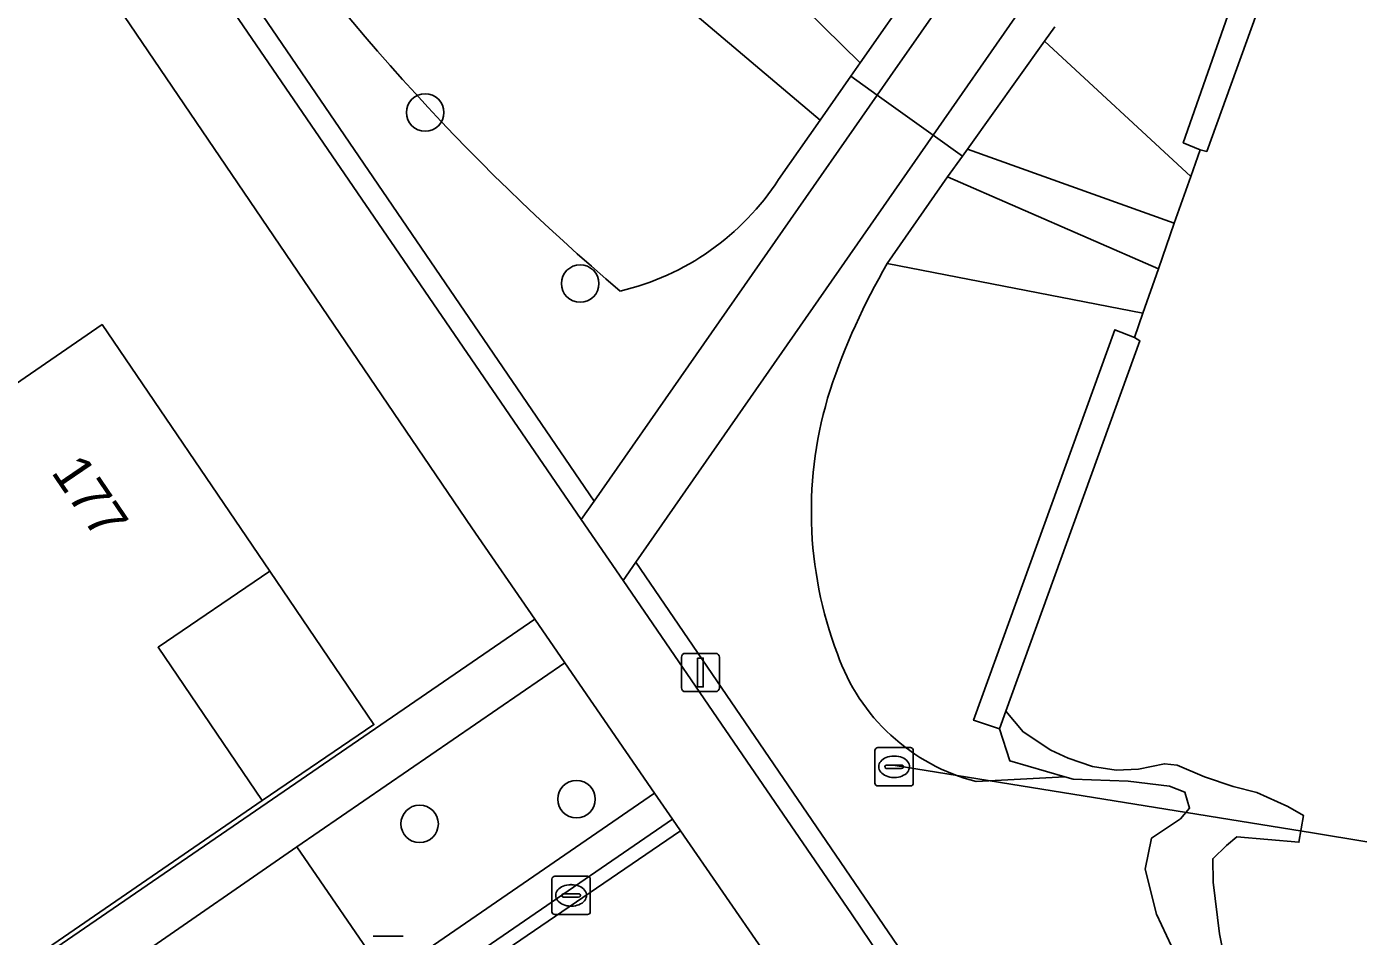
# Model space of a CAD drawing. Extents: x 155275 to 156265, y 382654 to 383635.
# Drawn here: x 155762.83 to 155797.88, y 383396.14 to 383419.88 of the extents above; entities that cross this region are included whole.
import ezdxf

# ---------------------------------------------------------------- set-up
doc = ezdxf.new("R2010")
doc.units = 0
for name, color, linetype in [('IMGEO_Boom', 7, 'Continuous'), ('IMGEO_Duiker', 7, 'Continuous'), ('IMGEO_Erf', 7, 'Continuous'), ('IMGEO_Groenvoorziening', 7, 'Continuous'), ('IMGEO_Haag', 7, 'Continuous'), ('IMGEO_Kademuur', 7, 'Continuous'), ('IMGEO_Kolk', 7, 'Continuous'), ('IMGEO_Lichtmast', 7, 'Continuous'), ('IMGEO_Meer_plas_ven_vijver', 7, 'Continuous'), ('IMGEO_Oever', 7, 'Continuous'), ('IMGEO_Pand', 7, 'Continuous'), ('IMGEO_Pand_nummerreeks', 7, 'Continuous'), ('IMGEO_Pand_overbouw', 7, 'Continuous'), ('IMGEO_Parkeervlak_open', 7, 'Continuous'), ('IMGEO_Rijbaan_lokaal_gesloten', 7, 'Continuous'), ('IMGEO_Rijbaan_lokaal_open', 7, 'Continuous'), ('IMGEO_Rioolput', 7, 'Continuous'), ('IMGEO_Voetpad_halfverhard', 7, 'Continuous'), ('IMGEO_Voetpad_open', 7, 'Continuous'), ('IMGEO_Waterloop', 7, 'Continuous')]:
    doc.layers.add(name, color=color, linetype=linetype)

msp = doc.modelspace()

# ---------------------------------------------------------------- linework, layer by layer
at = {"layer": 'IMGEO_Boom'}
for centre in [(155773.231, 383417.64), (155777.279, 383413.176), (155777.183, 383399.719), (155773.086, 383399.074)]:
    msp.add_circle(centre, 0.489, dxfattribs=at)
at = {"layer": 'IMGEO_Duiker'}
for points in [[(155787.259, 383416.5), (155786.497, 383417.047), (155785.035, 383418.096), (155784.346, 383418.59)], [(155797.819, 383398.608), (155796.402, 383398.837), (155785.502, 383400.6)]]:
    msp.add_lwpolyline(points, dxfattribs=at)
at = {"layer": 'IMGEO_Erf'}
for points in [[(155734.512, 383465.559), (155725.215, 383479.049), (155698.054, 383460.537), (155694.998, 383458.429), (155719.873, 383421.949), (155720.07, 383422.058), (155723.062, 383417.667), (155735.929, 383398.789), (155735.874, 383398.763), (155746.045, 383383.83), (155750.929, 383387.164), (155776.093, 383404.417), (155774.449, 383406.803)], [(155755.264, 383402.793), (155753.973, 383404.673), (155764.793, 383412.107), (155769.172, 383405.667), (155766.255, 383403.684), (155768.977, 383399.681), (155761.042, 383394.237), (155758.839, 383397.452), (155755.091, 383394.96), (155751.995, 383399.56), (155751.574, 383399.282), (155751.13, 383399.955)]]:
    msp.add_lwpolyline(points, close=True, dxfattribs=at)
at = {"layer": 'IMGEO_Groenvoorziening'}
for points in [[(155720.532, 383490.035), (155723.759, 383485.312), (155724.227, 383485.725), (155777.645, 383407.499), (155785.035, 383418.096), (155785.37, 383418.576), (155786.992, 383420.901), (155789.946, 383428.782), (155786.989, 383433.092)], [(155792.313, 383430.497), (155782.858, 383445.59), (155782.062, 383443.394), (155782.026, 383443.296), (155791.926, 383428.938), (155788.632, 383420.112), (155786.497, 383417.047), (155778.735, 383405.903), (155812.556, 383356.375)], [(155789.67, 383419.875), (155789.407, 383419.506), (155793.222, 383415.974), (155793.465, 383416.67), (155793.028, 383416.849), (155795.838, 383424.87), (155801.017, 383438.651), (155801.583, 383440.095), (155802.044, 383439.848)], [(155786.452, 383421.955), (155786.323, 383421.662), (155786.199, 383421.367), (155786.078, 383421.07), (155784.59, 383418.94), (155784.346, 383418.59), (155783.545, 383417.443), (155782.462, 383415.892)], [(155785.297, 383413.698), (155786.874, 383415.961), (155787.259, 383416.5), (155787.391, 383416.684), (155789.407, 383419.506), (155789.67, 383419.875)], [(155789.937, 383400.304), (155788.501, 383400.718), (155788.229, 383401.557), (155787.554, 383401.779), (155791.239, 383411.971), (155791.75, 383411.768), (155791.972, 383412.404), (155785.297, 383413.698)], [(155789.937, 383400.304), (155787.621, 383400.178)], [(155787.621, 383400.178), (155789.937, 383400.304)], [(155793.24, 383394.77), (155792.326, 383396.718), (155792.029, 383397.89), (155792.2, 383398.702), (155792.957, 383399.208), (155793.191, 383399.488), (155793.07, 383399.904), (155792.665, 383400.062), (155791.585, 383400.188), (155790.156, 383400.241), (155789.937, 383400.304)]]:
    msp.add_lwpolyline(points, dxfattribs=at)
for points in [[(155724.227, 383485.725), (155723.759, 383485.312), (155746.216, 383452.521), (155760.092, 383432.137), (155777.308, 383407.016), (155777.645, 383407.499)], [(155778.735, 383405.903), (155778.4, 383405.423), (155781.629, 383400.711), (155784.362, 383396.723), (155785.107, 383395.628), (155804.649, 383366.907), (155818.089, 383347.327), (155825.267, 383336.869), (155825.684, 383337.436), (155820.541, 383344.855), (155818.47, 383347.843), (155812.556, 383356.375)], [(155776.879, 383403.277), (155769.879, 383398.475), (155772.222, 383395.062), (155779.221, 383399.877)]]:
    msp.add_lwpolyline(points, close=True, dxfattribs=at)
for centre, radius, start, end in [((155816.344, 383457.794), 58.77, 214.23276, 229.68994), ((155776.754, 383419.603), 6.808, 283.3333, 326.9735), ((155800.504, 383404.845), 17.596, 149.7948, 161.6157), ((155800.504, 383404.845), 17.596, 149.7948, 161.6157), ((155793.797, 383407.226), 10.481, 162.404, 200.7737), ((155793.797, 383407.226), 10.481, 162.404, 200.7737), ((155788.917, 383405.224), 5.21, 199.2229, 255.6018), ((155788.917, 383405.224), 5.21, 199.2229, 255.6018)]:
    msp.add_arc(centre, radius, start, end, dxfattribs=at)
at = {"layer": 'IMGEO_Haag'}
for points in [[(155724.227, 383485.725), (155723.759, 383485.312), (155746.216, 383452.521), (155760.092, 383432.137), (155777.308, 383407.016), (155777.645, 383407.499)], [(155778.735, 383405.903), (155778.4, 383405.423), (155781.629, 383400.711), (155784.362, 383396.723), (155785.107, 383395.628), (155804.649, 383366.907), (155818.089, 383347.327), (155825.267, 383336.869), (155825.684, 383337.436), (155820.541, 383344.855), (155818.47, 383347.843), (155812.556, 383356.375)]]:
    msp.add_lwpolyline(points, close=True, dxfattribs=at)
at = {"layer": 'IMGEO_Kademuur'}
for points in [[(155800.706, 383436.152), (155801.722, 383438.959), (155802.044, 383439.848), (155801.583, 383440.095), (155801.017, 383438.651), (155795.838, 383424.87), (155793.028, 383416.849), (155793.465, 383416.67), (155793.639, 383416.625)], [(155788.229, 383401.557), (155788.397, 383402.02), (155791.895, 383411.685), (155791.75, 383411.768), (155791.239, 383411.971), (155787.554, 383401.779)]]:
    msp.add_lwpolyline(points, close=True, dxfattribs=at)
at = {"layer": 'IMGEO_Kolk'}
for p, q in [((155776.617, 383397.708), (155777.469, 383397.708)), ((155776.542, 383396.782), (155776.542, 383397.634)), ((155777.03, 383397.488), (155777.055, 383397.488)), ((155777.543, 383397.634), (155777.543, 383396.782)), ((155776.801, 383397.202), (155776.801, 383397.214)), ((155777.239, 383397.165), (155776.841, 383397.165)), ((155776.844, 383397.251), (155777.242, 383397.251)), ((155777.285, 383397.214), (155777.285, 383397.202)), ((155777.469, 383396.708), (155776.617, 383396.708)), ((155777.053, 383396.928), (155777.028, 383396.928))]:
    msp.add_line(p, q, dxfattribs=at)
for points in [[(155776.617, 383397.708), (155777.469, 383397.708)], [(155776.542, 383396.782), (155776.542, 383397.634)], [(155777.543, 383397.634), (155777.543, 383396.782)], [(155777.469, 383396.708), (155776.617, 383396.708)]]:
    msp.add_lwpolyline(points, dxfattribs=at)
for centre, radius, start, end in [((155776.619, 383397.632), 0.0765, 91.552, 178.448), ((155776.619, 383397.632), 0.0765, 91.552, 178.448), ((155777.467, 383397.632), 0.0765, 1.552, 88.448), ((155777.467, 383397.632), 0.0765, 1.552, 88.448), ((155776.841, 383397.211), 0.0403, 85.8775, 175.7526), ((155776.838, 383397.201), 0.0366, 178.938, 274.7102), ((155777.242, 383397.208), 0.043, 264.8664, 352.4533), ((155777.246, 383397.213), 0.0386, 1.7309, 96.639), ((155776.619, 383396.784), 0.0765, 181.552, 268.448), ((155776.619, 383396.784), 0.0765, 181.552, 268.448), ((155777.467, 383396.784), 0.0765, 271.552, 358.448), ((155777.467, 383396.784), 0.0765, 271.552, 358.448)]:
    msp.add_arc(centre, radius, start, end, dxfattribs=at)
for centre, major_axis, ratio, start_param, end_param in [((155777.029, 383397.208), (-0.387, 0.002), 0.722429, 4.712389, 7.853982), ((155777.054, 383397.208), (-0.39, 0.002), 0.717154, 1.570796, 4.712389)]:
    msp.add_ellipse(centre, major_axis=major_axis, ratio=ratio, start_param=start_param, end_param=end_param, dxfattribs=at)
at = {"layer": 'IMGEO_Lichtmast'}
for p, q in [((155779.924, 383402.625), (155779.924, 383403.425)), ((155779.924, 383403.425), (155779.924, 383402.625)), ((155780.024, 383403.525), (155780.814, 383403.525)), ((155780.814, 383403.525), (155780.024, 383403.525)), ((155780.914, 383403.425), (155780.914, 383402.625)), ((155780.914, 383402.625), (155780.914, 383403.425)), ((155780.814, 383402.525), (155780.024, 383402.525)), ((155780.024, 383402.525), (155780.814, 383402.525)), ((155771.869, 383396.145), (155772.659, 383396.145)), ((155772.659, 383396.145), (155771.869, 383396.145))]:
    msp.add_line(p, q, dxfattribs=at)
msp.add_lwpolyline([(155780.344, 383403.4), (155780.494, 383403.4), (155780.494, 383402.65), (155780.344, 383402.65), (155780.344, 383403.4)], dxfattribs=at)
for centre, start, end in [((155780.024, 383403.425), 90, 180), ((155780.024, 383403.425), 90, 180), ((155780.814, 383403.425), 0, 90), ((155780.814, 383403.425), 360, 90), ((155780.024, 383402.625), 180, 270), ((155780.024, 383402.625), 180, 270), ((155780.814, 383402.625), 270, 0), ((155780.814, 383402.625), 270, 0)]:
    msp.add_arc(centre, 0.1, start, end, dxfattribs=at)
at = {"layer": 'IMGEO_Meer_plas_ven_vijver'}
msp.add_lwpolyline([(155800.706, 383436.152), (155793.639, 383416.625), (155793.465, 383416.67), (155793.222, 383415.974), (155792.794, 383414.752), (155792.377, 383413.56), (155791.972, 383412.404), (155791.75, 383411.768), (155791.895, 383411.685), (155788.397, 383402.02), (155788.847, 383401.476), (155789.568, 383401), (155790.019, 383400.793), (155790.66, 383400.573), (155791.273, 383400.477), (155791.855, 383400.501), (155792.536, 383400.645), (155792.867, 383400.609), (155793.583, 383400.304), (155794.333, 383400.053), (155794.946, 383399.889), (155795.758, 383399.526), (155796.165, 383399.294), (155796.047, 383398.596), (155794.424, 383398.74), (155794.157, 383398.511), (155793.799, 383398.165), (155793.809, 383397.55), (155793.975, 383396.206), (155794.22, 383394.98)], dxfattribs=at)
at = {"layer": 'IMGEO_Oever'}
for points in [[(155746.049, 383462.013), (155749.851, 383457.256), (155756.539, 383449.702), (155771.747, 383431.539), (155784.59, 383418.94), (155786.078, 383421.07), (155786.199, 383421.367), (155786.323, 383421.662), (155786.452, 383421.955)], [(155782.462, 383415.892), (155783.545, 383417.443), (155778.762, 383421.492), (155773.01, 383427.092), (155766.987, 383433.504), (155758.776, 383442.965), (155755.32, 383447.516), (155753.026, 383450.252), (155750.156, 383453.198), (155747.4, 383456.9), (155745.459, 383459.436)], [(155788.397, 383402.02), (155788.229, 383401.557), (155788.501, 383400.718), (155789.937, 383400.304), (155790.156, 383400.241), (155791.585, 383400.188), (155792.665, 383400.062), (155793.07, 383399.904), (155793.191, 383399.488), (155792.957, 383399.208), (155792.2, 383398.702), (155792.029, 383397.89), (155792.326, 383396.718), (155793.24, 383394.77)], [(155794.22, 383394.98), (155793.975, 383396.206), (155793.809, 383397.55), (155793.799, 383398.165), (155794.157, 383398.511), (155794.424, 383398.74), (155796.047, 383398.596), (155796.165, 383399.294), (155795.758, 383399.526), (155794.946, 383399.889), (155794.333, 383400.053), (155793.583, 383400.304), (155792.867, 383400.609), (155792.536, 383400.645), (155791.855, 383400.501), (155791.273, 383400.477), (155790.66, 383400.573), (155790.019, 383400.793), (155789.568, 383401), (155788.847, 383401.476), (155788.397, 383402.02)]]:
    msp.add_lwpolyline(points, dxfattribs=at)
for points in [[(155789.407, 383419.506), (155787.391, 383416.684), (155792.794, 383414.752), (155793.222, 383415.974)], [(155786.874, 383415.961), (155785.297, 383413.698), (155791.972, 383412.404), (155792.377, 383413.56)]]:
    msp.add_lwpolyline(points, close=True, dxfattribs=at)
for centre, radius, start, end in [((155816.344, 383457.794), 58.77, 214.23276, 229.68994), ((155776.754, 383419.603), 6.808, 283.3333, 326.9735)]:
    msp.add_arc(centre, radius, start, end, dxfattribs=at)
at = {"layer": 'IMGEO_Pand'}
msp.add_lwpolyline([(155751.574, 383399.282), (155751.995, 383399.56), (155755.091, 383394.96), (155758.839, 383397.452), (155761.042, 383394.237), (155768.977, 383399.681), (155766.255, 383403.684), (155769.172, 383405.667), (155764.793, 383412.107), (155753.973, 383404.673), (155755.264, 383402.793), (155751.13, 383399.955)], close=True, dxfattribs=at)
at = {"layer": 'IMGEO_Pand_overbouw'}
msp.add_lwpolyline([(155768.977, 383399.681), (155771.894, 383401.665), (155769.172, 383405.667), (155766.255, 383403.684)], close=True, dxfattribs=at)
at = {"layer": 'IMGEO_Parkeervlak_open'}
msp.add_lwpolyline([(155768.096, 383392.242), (155768.588, 383391.566), (155772.686, 383394.39), (155772.222, 383395.062), (155769.879, 383398.475), (155765.776, 383395.635)], close=True, dxfattribs=at)
at = {"layer": 'IMGEO_Rijbaan_lokaal_gesloten'}
msp.add_lwpolyline([(155721.169, 383358.828), (155779.897, 383398.895), (155779.69, 383399.195), (155772.686, 383394.39)], dxfattribs=at)
at = {"layer": 'IMGEO_Rijbaan_lokaal_open'}
msp.add_lwpolyline([(155782.106, 383395.69), (155779.897, 383398.895), (155721.169, 383358.828), (155661.404, 383317.986), (155661.244, 383318.235), (155660.115, 383317.515)], dxfattribs=at)
at = {"layer": 'IMGEO_Rioolput'}
for p, q in [((155784.977, 383400.139), (155784.977, 383400.991)), ((155785.052, 383401.065), (155785.904, 383401.065)), ((155785.465, 383400.845), (155785.49, 383400.845)), ((155785.978, 383400.991), (155785.978, 383400.139)), ((155785.236, 383400.559), (155785.236, 383400.571)), ((155785.674, 383400.522), (155785.276, 383400.522)), ((155785.279, 383400.608), (155785.677, 383400.608)), ((155785.72, 383400.571), (155785.72, 383400.559)), ((155785.488, 383400.285), (155785.463, 383400.285)), ((155785.904, 383400.065), (155785.052, 383400.065))]:
    msp.add_line(p, q, dxfattribs=at)
for points in [[(155784.977, 383400.139), (155784.977, 383400.991)], [(155785.052, 383401.065), (155785.904, 383401.065)], [(155785.978, 383400.991), (155785.978, 383400.139)], [(155785.904, 383400.065), (155785.052, 383400.065)]]:
    msp.add_lwpolyline(points, dxfattribs=at)
for centre, radius, start, end in [((155785.054, 383400.989), 0.0765, 91.552, 178.448), ((155785.054, 383400.989), 0.0765, 91.552, 178.448), ((155785.902, 383400.989), 0.0765, 1.552, 88.448), ((155785.902, 383400.989), 0.0765, 1.552, 88.448), ((155785.276, 383400.568), 0.0403, 85.8775, 175.7526), ((155785.273, 383400.558), 0.0366, 178.938, 274.7102), ((155785.677, 383400.565), 0.043, 264.8664, 352.4533), ((155785.681, 383400.57), 0.0386, 1.7309, 96.639), ((155785.054, 383400.141), 0.0765, 181.552, 268.448), ((155785.054, 383400.141), 0.0765, 181.552, 268.448), ((155785.902, 383400.141), 0.0765, 271.552, 358.448), ((155785.902, 383400.141), 0.0765, 271.552, 358.448)]:
    msp.add_arc(centre, radius, start, end, dxfattribs=at)
for centre, major_axis, ratio, start_param, end_param in [((155785.464, 383400.565), (-0.387, 0.002), 0.722429, 4.712389, 7.853982), ((155785.489, 383400.565), (-0.39, 0.002), 0.717154, 1.570796, 4.712389)]:
    msp.add_ellipse(centre, major_axis=major_axis, ratio=ratio, start_param=start_param, end_param=end_param, dxfattribs=at)
at = {"layer": 'IMGEO_Voetpad_halfverhard'}
msp.add_lwpolyline([(155786.989, 383433.092), (155789.946, 383428.782), (155786.992, 383420.901), (155785.37, 383418.576), (155785.035, 383418.096), (155777.645, 383407.499), (155777.308, 383407.016), (155778.4, 383405.423), (155778.735, 383405.903), (155786.497, 383417.047), (155788.632, 383420.112), (155791.926, 383428.938), (155782.026, 383443.296), (155781.307, 383441.344), (155786.215, 383434.22)], dxfattribs=at)
at = {"layer": 'IMGEO_Voetpad_open'}
for points in [[(155785.107, 383395.628), (155784.362, 383396.723), (155781.629, 383400.711), (155778.4, 383405.423), (155777.308, 383407.016), (155760.092, 383432.137), (155746.216, 383452.521), (155723.759, 383485.312)], [(155725.215, 383479.049), (155734.512, 383465.559), (155774.449, 383406.803), (155776.093, 383404.417), (155776.879, 383403.277), (155779.221, 383399.877), (155779.69, 383399.195), (155779.897, 383398.895), (155782.106, 383395.69)], [(155757.527, 383390.034), (155765.776, 383395.635), (155769.879, 383398.475), (155776.879, 383403.277), (155776.093, 383404.417), (155750.929, 383387.164), (155746.045, 383383.83), (155744.93, 383383.103), (155746.215, 383381.223)]]:
    msp.add_lwpolyline(points, dxfattribs=at)
msp.add_lwpolyline([(155772.222, 383395.062), (155772.686, 383394.39), (155779.69, 383399.195), (155779.221, 383399.877)], close=True, dxfattribs=at)
at = {"layer": 'IMGEO_Waterloop'}
msp.add_lwpolyline([(155745.459, 383459.436), (155747.4, 383456.9), (155750.156, 383453.198), (155753.026, 383450.252), (155755.32, 383447.516), (155758.776, 383442.965), (155766.987, 383433.504), (155773.01, 383427.092), (155778.762, 383421.492), (155783.545, 383417.443), (155784.346, 383418.59), (155784.59, 383418.94), (155771.747, 383431.539), (155756.539, 383449.702), (155749.851, 383457.256), (155746.049, 383462.013)], dxfattribs=at)
msp.add_lwpolyline([(155787.391, 383416.684), (155787.259, 383416.5), (155786.874, 383415.961), (155792.377, 383413.56), (155792.794, 383414.752)], close=True, dxfattribs=at)

# ---------------------------------------------------------------- texts
at = {"layer": 'IMGEO_Pand_nummerreeks'}
msp.add_text('177', height=1, rotation=304.2191, dxfattribs=at).set_placement((155763.446, 383408.254))

doc.saveas('drawing.dxf')
